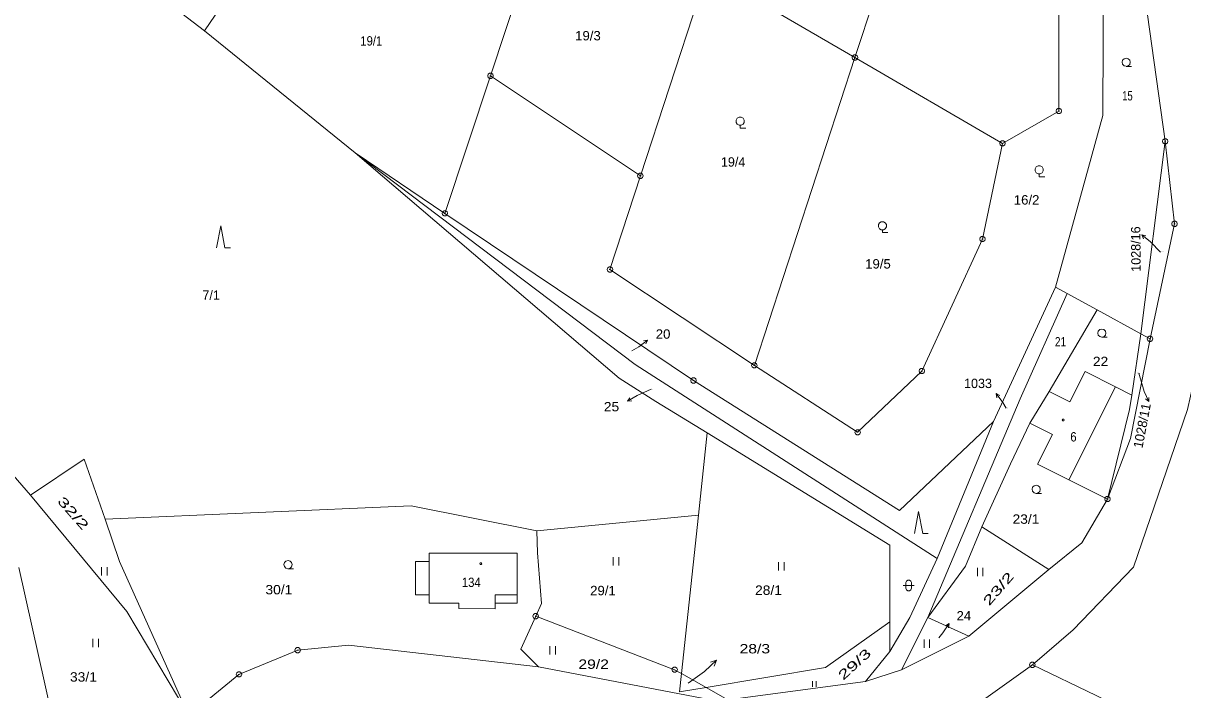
# Model space of a CAD drawing. Extents: x -687390 to -684106, y -954833 to -951648.
# Drawn here: x -686842.5 to -686632.4, y -952373.7 to -952252.9 of the extents above; entities that cross this region are included whole.
import ezdxf
from ezdxf.enums import TextEntityAlignment as Align

# ---------------------------------------------------------------- set-up
doc = ezdxf.new("R2010")
doc.units = 0
doc.header["$LTSCALE"] = 0.68
for name, color, linetype, lineweight in [('1', 7, 'Continuous', 13), ('3', 7, 'Continuous', 13), ('4', 7, 'Continuous', 13), ('5', 7, 'Continuous', 13), ('7', 7, 'Continuous', 13), ('8', 7, 'Continuous', 13)]:
    doc.layers.add(name, color=color, linetype=linetype, lineweight=lineweight)
doc.layers.add('2', color=7, linetype='Continuous')

msp = doc.modelspace()

# ---------------------------------------------------------------- linework, layer by layer
at = {"layer": '1'}
for p, q in [((-686675.65, -952209.59), (-686691.8, -952259.08)), ((-686635.56, -952274.27), (-686640.5, -952239.1)), ((-686718.58, -952243.49), (-686730.67, -952280.52)), ((-686809.68, -952254.23), (-686782.38, -952276.38)), ((-686691.8, -952259.08), (-686710.02, -952314.88)), ((-686757.85, -952262.42), (-686766.11, -952287.32)), ((-686782.38, -952276.38), (-686766.11, -952287.32)), ((-686766.11, -952287.32), (-686721.05, -952317.63)), ((-686653.31, -952301.85), (-686655.44, -952300.69)), ((-686653.31, -952301.85), (-686661.86, -952320.95)), ((-686647.9, -952304.83), (-686653.31, -952301.85)), ((-686647.9, -952304.83), (-686656.58, -952319.59)), ((-686641.62, -952320.24), (-686639.97, -952309.17)), ((-686650.06, -952315.96), (-686644.57, -952318.75)), ((-686683.73, -952341.14), (-686721.05, -952317.63)), ((-686644.57, -952318.75), (-686641.62, -952320.24)), ((-686678.57, -952360.57), (-686661.86, -952320.95)), ((-686660.07, -952325.36), (-686663.63, -952332.73)), ((-686656.02, -952327.37), (-686658.68, -952332.76)), ((-686668.79, -952344.1), (-686663.63, -952332.73)), ((-686658.68, -952332.76), (-686653.03, -952335.59)), ((-686653.03, -952335.59), (-686646.02, -952339.1)), ((-686827.68, -952342.74), (-686825.09, -952350.41)), ((-686685.45, -952347.42), (-686685.47, -952361.33)), ((-686768.96, -952348.91), (-686752.99, -952348.9)), ((-686752.99, -952348.9), (-686752.99, -952356.46)), ((-686676.91, -952349.84), (-686681.85, -952360.57)), ((-686843.35, -952351.48), (-686834.2, -952392.4)), ((-686812.53, -952378.29), (-686825.09, -952350.41)), ((-686756.99, -952358.96), (-686756.99, -952357.96)), ((-686685.48, -952366.74), (-686681.85, -952360.57)), ((-686671.14, -952363.91), (-686678.57, -952360.57)), ((-686671.14, -952363.91), (-686683.35, -952370.03)), ((-686723.22, -952370.73), (-686718.74, -952373.26)), ((-686714.84, -952375.47), (-686689.87, -952372.16))]:
    msp.add_line(p, q, dxfattribs=at)
for points in [[(-686731.65, -952183.41), (-686703.29, -952196.66), (-686675.65, -952209.59), (-686666.23, -952213.98), (-686660.17, -952222.54), (-686654.82, -952243.48), (-686654.84, -952268.78), (-686665.05, -952274.64), (-686691.8, -952259.08), (-686718.58, -952243.49), (-686746.23, -952227.39)], [(-686822.25, -952244.56), (-686809.68, -952254.23), (-686788.01, -952222.33)], [(-686757.85, -952262.42), (-686752.26, -952245.56), (-686788.01, -952222.33)], [(-686646.76, -952242.06), (-686646.86, -952269.57), (-686655.44, -952300.69)], [(-686665.05, -952274.64), (-686668.68, -952291.99), (-686679.67, -952315.89), (-686691.31, -952327), (-686710.02, -952314.88), (-686736.2, -952297.49), (-686730.67, -952280.52), (-686757.85, -952262.42)], [(-686635.56, -952274.27), (-686639.97, -952309.17), (-686647.9, -952304.83)], [(-686639.97, -952309.17), (-686638.31, -952310.06), (-686633.87, -952289.22), (-686635.56, -952274.27)], [(-686782.38, -952276.38), (-686731.61, -952314.68), (-686676.91, -952349.84), (-686666.7, -952325.03)], [(-686782.38, -952276.38), (-686734.55, -952317.16), (-686727.87, -952321.42), (-686718.58, -952327.11)], [(-686623.46, -952279.64), (-686624.96, -952282.62), (-686626.61, -952301.13), (-686631.53, -952322.87), (-686641.34, -952351.45), (-686652.22, -952362.81), (-686659.63, -952369.13), (-686648.08, -952374.71), (-686634.56, -952381.48), (-686619.46, -952386.48), (-686599.68, -952383.77), (-686603.98, -952392.18), (-686598.64, -952402.07), (-686585.34, -952406.85), (-686566.31, -952418.36), (-686550.51, -952430.86), (-686541.6, -952432.87), (-686525.56, -952458.37), (-686521.93, -952464.8)], [(-686866.54, -952281.02), (-686856.6, -952300.81), (-686857.44, -952303.87), (-686875.46, -952318.53), (-686854.46, -952336.7), (-686846.31, -952332.52), (-686841.22, -952338.37), (-686831.5, -952331.87), (-686827.68, -952342.74), (-686772.24, -952340.34), (-686749.44, -952344.82), (-686720.16, -952342.03), (-686723.22, -952370.73)], [(-686683.73, -952341.14), (-686666.7, -952325.03), (-686655.44, -952300.69)], [(-686638.31, -952310.06), (-686641.83, -952328.1), (-686646.02, -952339.1)], [(-686650.06, -952315.96), (-686652.82, -952321.45), (-686656.58, -952319.59), (-686660.07, -952325.36), (-686656.02, -952327.37)], [(-686646.02, -952339.1), (-686642.02, -952322.89), (-686641.62, -952320.24)], [(-686720.16, -952342.03), (-686718.58, -952327.11), (-686685.45, -952347.42)], [(-686812.53, -952378.29), (-686823.77, -952359.47), (-686841.22, -952338.37)], [(-686646.02, -952339.1), (-686650.68, -952347.05), (-686656.68, -952351.88)], [(-686749.44, -952344.82), (-686749.34, -952348.85), (-686748.59, -952357.99)], [(-686678.57, -952360.57), (-686671.73, -952351.28), (-686668.79, -952344.1)], [(-686668.79, -952344.1), (-686656.68, -952351.88), (-686671.14, -952363.91)], [(-686768.96, -952348.91), (-686768.97, -952350.4), (-686771.41, -952350.4), (-686771.41, -952356.42), (-686768.98, -952356.42), (-686768.98, -952357.93)], [(-686756.99, -952358.96), (-686763.56, -952358.93), (-686763.57, -952357.94), (-686768.98, -952357.93)], [(-686752.99, -952356.46), (-686752.99, -952357.97), (-686756.99, -952357.96)], [(-686748.59, -952357.99), (-686749.65, -952360.33), (-686752.37, -952366.32)], [(-686749.65, -952360.33), (-686724.47, -952370.01), (-686723.22, -952370.73), (-686723.57, -952374.05), (-686718.74, -952373.26)], [(-686685.48, -952366.74), (-686689.87, -952372.16), (-686683.35, -952370.03), (-686678.57, -952360.57)], [(-686718.74, -952373.26), (-686697.11, -952369.64), (-686685.47, -952361.33), (-686685.48, -952366.74)], [(-686749.13, -952369.49), (-686783.59, -952365.56), (-686792.79, -952366.48), (-686803.43, -952370.86), (-686812.53, -952378.29)], [(-686752.37, -952366.32), (-686749.13, -952369.49), (-686716.62, -952375.7)], [(-686701.59, -952385.52), (-686685.6, -952381.86), (-686670.21, -952376.71), (-686659.63, -952369.13)], [(-686716.62, -952375.7), (-686714.84, -952375.47), (-686718.74, -952373.26)]]:
    msp.add_lwpolyline(points, dxfattribs=at)
at = {"layer": '3'}
for p, q in [((-686735.6, -952349.62), (-686735.6, -952351.12)), ((-686734.6, -952351.12), (-686734.6, -952349.62)), ((-686828.34, -952351.43), (-686828.34, -952352.93)), ((-686827.34, -952352.93), (-686827.34, -952351.43)), ((-686705.65, -952350.55), (-686705.65, -952352.05)), ((-686704.65, -952352.05), (-686704.65, -952350.55)), ((-686669.6, -952351.57), (-686669.6, -952353.07)), ((-686668.6, -952353.07), (-686668.6, -952351.57)), ((-686829.91, -952364.42), (-686829.91, -952365.92)), ((-686828.91, -952365.92), (-686828.91, -952364.42)), ((-686679.28, -952364.53), (-686679.28, -952366.03)), ((-686678.28, -952366.03), (-686678.28, -952364.53)), ((-686747.08, -952365.77), (-686747.08, -952367.27)), ((-686746.08, -952367.27), (-686746.08, -952365.77)), ((-686699.495, -952372.085), (-686699.495, -952373.09)), ((-686698.825, -952373.09), (-686698.825, -952372.085))]:
    msp.add_line(p, q, dxfattribs=at)
for points in [[(-686642.63, -952260.68), (-686643.01, -952260.58), (-686643.28, -952260.31), (-686643.38, -952259.94), (-686643.28, -952259.57), (-686643.01, -952259.3), (-686642.64, -952259.2), (-686642.27, -952259.3), (-686642, -952259.57), (-686641.9, -952259.95), (-686642, -952260.33), (-686642.27, -952260.6), (-686642.65, -952260.7), (-686641.65, -952260.7)], [(-686712.61, -952271.36), (-686712.8, -952271.36), (-686713.14, -952271.17), (-686713.33, -952270.83), (-686713.33, -952270.44), (-686713.14, -952270.1), (-686712.8, -952269.91), (-686712.41, -952269.91), (-686712.07, -952270.1), (-686711.88, -952270.44), (-686711.88, -952270.83), (-686712.07, -952271.17), (-686712.41, -952271.36), (-686712.6, -952271.36), (-686712.6, -952271.89), (-686711.6, -952271.89)], [(-686658.41, -952280.17), (-686658.6, -952280.17), (-686658.94, -952279.98), (-686659.13, -952279.64), (-686659.13, -952279.25), (-686658.94, -952278.91), (-686658.6, -952278.72), (-686658.21, -952278.72), (-686657.87, -952278.91), (-686657.68, -952279.25), (-686657.68, -952279.64), (-686657.87, -952279.98), (-686658.21, -952280.17), (-686658.4, -952280.17), (-686658.4, -952280.7), (-686657.4, -952280.7)], [(-686686.83, -952290.29), (-686687.02, -952290.29), (-686687.36, -952290.1), (-686687.55, -952289.76), (-686687.55, -952289.37), (-686687.36, -952289.03), (-686687.02, -952288.84), (-686686.63, -952288.84), (-686686.29, -952289.03), (-686686.1, -952289.37), (-686686.1, -952289.76), (-686686.29, -952290.1), (-686686.63, -952290.29), (-686686.82, -952290.29), (-686686.82, -952290.82), (-686685.82, -952290.82)], [(-686807.49, -952293.58), (-686806.74, -952289.58), (-686805.99, -952293.58), (-686804.99, -952293.58)], [(-686647.04, -952309.76), (-686647.42, -952309.66), (-686647.69, -952309.39), (-686647.79, -952309.02), (-686647.69, -952308.65), (-686647.42, -952308.38), (-686647.05, -952308.28), (-686646.68, -952308.38), (-686646.41, -952308.65), (-686646.31, -952309.03), (-686646.41, -952309.41), (-686646.68, -952309.68), (-686647.06, -952309.78), (-686646.06, -952309.78)], [(-686658.94, -952338.06), (-686659.32, -952337.96), (-686659.59, -952337.69), (-686659.69, -952337.32), (-686659.59, -952336.95), (-686659.32, -952336.68), (-686658.95, -952336.58), (-686658.58, -952336.68), (-686658.31, -952336.95), (-686658.21, -952337.33), (-686658.31, -952337.71), (-686658.58, -952337.98), (-686658.96, -952338.08), (-686657.96, -952338.08)], [(-686681.02, -952345.34), (-686680.27, -952341.34), (-686679.52, -952345.34), (-686678.52, -952345.34)], [(-686794.53, -952351.71), (-686794.91, -952351.61), (-686795.18, -952351.34), (-686795.28, -952350.97), (-686795.18, -952350.6), (-686794.91, -952350.33), (-686794.54, -952350.23), (-686794.17, -952350.33), (-686793.9, -952350.6), (-686793.8, -952350.98), (-686793.9, -952351.36), (-686794.17, -952351.63), (-686794.55, -952351.73), (-686793.55, -952351.73)], [(-686683.08, -952354.74), (-686681.81, -952354.74), (-686681.08, -952354.74)]]:
    msp.add_lwpolyline(points, dxfattribs=at)
msp.add_lwpolyline([(-686682.58, -952354.24), (-686682.48, -952353.95), (-686682.23, -952353.77), (-686681.92, -952353.77), (-686681.67, -952353.95), (-686681.57, -952354.24), (-686681.57, -952355.24), (-686681.67, -952355.53), (-686681.92, -952355.71), (-686682.23, -952355.71), (-686682.48, -952355.53), (-686682.58, -952355.24)], close=True, dxfattribs=at)
at = {"layer": '4'}
for p, q in [((-686653.03, -952335.59), (-686644.57, -952318.75)), ((-686768.97, -952350.4), (-686768.98, -952356.42))]:
    msp.add_line(p, q, dxfattribs=at)
msp.add_lwpolyline([(-686756.99, -952357.96), (-686756.98, -952356.47), (-686752.99, -952356.46)], dxfattribs=at)
at = {"layer": '5'}
for points in [[(-686653.94, -952324.6), (-686653.85, -952324.75), (-686653.94, -952324.9), (-686654.12, -952324.9), (-686654.21, -952324.75), (-686654.12, -952324.6)], [(-686759.53, -952350.66), (-686759.44, -952350.81), (-686759.53, -952350.96), (-686759.71, -952350.96), (-686759.8, -952350.81), (-686759.71, -952350.66)]]:
    msp.add_lwpolyline(points, close=True, dxfattribs=at)
at = {"layer": '7'}
for p, q in [((-686639.788, -952291.235), (-686638.21, -952292.48)), ((-686636.42, -952294.35), (-686638.21, -952292.48)), ((-686732.24, -952312.23), (-686730.98, -952311.51)), ((-686729.389, -952310.281), (-686730.98, -952311.51)), ((-686640.37, -952316.28), (-686639.39, -952319.59)), ((-686733.003, -952321.361), (-686731.29, -952320.31)), ((-686728.71, -952319.19), (-686731.29, -952320.31)), ((-686666.227, -952319.986), (-686664.99, -952321.57)), ((-686638.553, -952321.418), (-686639.39, -952319.59)), ((-686664.38, -952322.64), (-686664.99, -952321.57)), ((-686674.738, -952361.659), (-686675.84, -952363.34)), ((-686676.61, -952364.21), (-686675.84, -952363.34)), ((-686716.9, -952368.309), (-686719.09, -952370.36)), ((-686722.04, -952372.43), (-686719.09, -952370.36))]:
    msp.add_line(p, q, dxfattribs=at)
for points in [[(-686639.47, -952291.913), (-686639.788, -952291.235), (-686639.055, -952291.387)], [(-686730.124, -952310.426), (-686729.389, -952310.281), (-686729.715, -952310.956)], [(-686666.079, -952320.72), (-686666.227, -952319.986), (-686665.551, -952320.308)], [(-686732.257, -952321.296), (-686733.003, -952321.361), (-686732.607, -952320.725)], [(-686638.528, -952320.669), (-686638.553, -952321.418), (-686639.137, -952320.948)], [(-686675.386, -952362.036), (-686674.738, -952361.659), (-686674.825, -952362.403)], [(-686717.972, -952368.628), (-686716.9, -952368.309), (-686717.288, -952369.358)]]:
    msp.add_lwpolyline(points, dxfattribs=at)
at = {"layer": '8'}
for p, q in [((-686691.92, -952259.08), (-686691.68, -952259.08)), ((-686757.97, -952262.42), (-686757.73, -952262.42)), ((-686654.96, -952268.78), (-686654.72, -952268.78)), ((-686635.68, -952274.27), (-686635.44, -952274.27)), ((-686665.17, -952274.64), (-686664.93, -952274.64)), ((-686730.79, -952280.52), (-686730.55, -952280.52)), ((-686766.23, -952287.32), (-686765.99, -952287.32)), ((-686633.99, -952289.22), (-686633.75, -952289.22)), ((-686668.8, -952291.99), (-686668.56, -952291.99)), ((-686736.32, -952297.49), (-686736.08, -952297.49)), ((-686638.43, -952310.06), (-686638.19, -952310.06)), ((-686710.14, -952314.88), (-686709.9, -952314.88)), ((-686679.79, -952315.89), (-686679.55, -952315.89)), ((-686721.17, -952317.63), (-686720.93, -952317.63)), ((-686691.43, -952327), (-686691.19, -952327)), ((-686646.14, -952339.1), (-686645.9, -952339.1)), ((-686749.77, -952360.33), (-686749.53, -952360.33)), ((-686792.91, -952366.48), (-686792.67, -952366.48)), ((-686803.55, -952370.86), (-686803.31, -952370.86)), ((-686724.59, -952370.01), (-686724.35, -952370.01)), ((-686659.75, -952369.13), (-686659.51, -952369.13))]:
    msp.add_line(p, q, dxfattribs=at)
for points in [[(-686691.65, -952258.6), (-686691.4, -952258.78), (-686691.3, -952259.07), (-686691.4, -952259.36), (-686691.65, -952259.54), (-686691.96, -952259.54), (-686692.21, -952259.36), (-686692.31, -952259.07), (-686692.21, -952258.78), (-686691.96, -952258.6)], [(-686757.7, -952261.94), (-686757.45, -952262.12), (-686757.35, -952262.41), (-686757.45, -952262.7), (-686757.7, -952262.88), (-686758.01, -952262.88), (-686758.26, -952262.7), (-686758.36, -952262.41), (-686758.26, -952262.12), (-686758.01, -952261.94)], [(-686654.69, -952268.3), (-686654.44, -952268.48), (-686654.34, -952268.77), (-686654.44, -952269.06), (-686654.69, -952269.24), (-686655, -952269.24), (-686655.25, -952269.06), (-686655.35, -952268.77), (-686655.25, -952268.48), (-686655, -952268.3)], [(-686664.9, -952274.16), (-686664.65, -952274.34), (-686664.55, -952274.63), (-686664.65, -952274.92), (-686664.9, -952275.1), (-686665.21, -952275.1), (-686665.46, -952274.92), (-686665.56, -952274.63), (-686665.46, -952274.34), (-686665.21, -952274.16)], [(-686635.41, -952273.79), (-686635.16, -952273.97), (-686635.06, -952274.26), (-686635.16, -952274.55), (-686635.41, -952274.73), (-686635.72, -952274.73), (-686635.97, -952274.55), (-686636.07, -952274.26), (-686635.97, -952273.97), (-686635.72, -952273.79)], [(-686730.52, -952280.04), (-686730.27, -952280.22), (-686730.17, -952280.51), (-686730.27, -952280.8), (-686730.52, -952280.98), (-686730.83, -952280.98), (-686731.08, -952280.8), (-686731.18, -952280.51), (-686731.08, -952280.22), (-686730.83, -952280.04)], [(-686765.96, -952286.84), (-686765.71, -952287.02), (-686765.61, -952287.31), (-686765.71, -952287.6), (-686765.96, -952287.78), (-686766.27, -952287.78), (-686766.52, -952287.6), (-686766.62, -952287.31), (-686766.52, -952287.02), (-686766.27, -952286.84)], [(-686633.72, -952288.74), (-686633.47, -952288.92), (-686633.37, -952289.21), (-686633.47, -952289.5), (-686633.72, -952289.68), (-686634.03, -952289.68), (-686634.28, -952289.5), (-686634.38, -952289.21), (-686634.28, -952288.92), (-686634.03, -952288.74)], [(-686668.53, -952291.51), (-686668.28, -952291.69), (-686668.18, -952291.98), (-686668.28, -952292.27), (-686668.53, -952292.45), (-686668.84, -952292.45), (-686669.09, -952292.27), (-686669.19, -952291.98), (-686669.09, -952291.69), (-686668.84, -952291.51)], [(-686736.05, -952297.01), (-686735.8, -952297.19), (-686735.7, -952297.48), (-686735.8, -952297.77), (-686736.05, -952297.95), (-686736.36, -952297.95), (-686736.61, -952297.77), (-686736.71, -952297.48), (-686736.61, -952297.19), (-686736.36, -952297.01)], [(-686638.16, -952309.58), (-686637.91, -952309.76), (-686637.81, -952310.05), (-686637.91, -952310.34), (-686638.16, -952310.52), (-686638.47, -952310.52), (-686638.72, -952310.34), (-686638.82, -952310.05), (-686638.72, -952309.76), (-686638.47, -952309.58)], [(-686709.87, -952314.4), (-686709.62, -952314.58), (-686709.52, -952314.87), (-686709.62, -952315.16), (-686709.87, -952315.34), (-686710.18, -952315.34), (-686710.43, -952315.16), (-686710.53, -952314.87), (-686710.43, -952314.58), (-686710.18, -952314.4)], [(-686679.52, -952315.41), (-686679.27, -952315.59), (-686679.17, -952315.88), (-686679.27, -952316.17), (-686679.52, -952316.35), (-686679.83, -952316.35), (-686680.08, -952316.17), (-686680.18, -952315.88), (-686680.08, -952315.59), (-686679.83, -952315.41)], [(-686720.9, -952317.15), (-686720.65, -952317.33), (-686720.55, -952317.62), (-686720.65, -952317.91), (-686720.9, -952318.09), (-686721.21, -952318.09), (-686721.46, -952317.91), (-686721.56, -952317.62), (-686721.46, -952317.33), (-686721.21, -952317.15)], [(-686691.16, -952326.52), (-686690.91, -952326.7), (-686690.81, -952326.99), (-686690.91, -952327.28), (-686691.16, -952327.46), (-686691.47, -952327.46), (-686691.72, -952327.28), (-686691.82, -952326.99), (-686691.72, -952326.7), (-686691.47, -952326.52)], [(-686645.87, -952338.62), (-686645.62, -952338.8), (-686645.52, -952339.09), (-686645.62, -952339.38), (-686645.87, -952339.56), (-686646.18, -952339.56), (-686646.43, -952339.38), (-686646.53, -952339.09), (-686646.43, -952338.8), (-686646.18, -952338.62)], [(-686749.5, -952359.85), (-686749.25, -952360.03), (-686749.15, -952360.32), (-686749.25, -952360.61), (-686749.5, -952360.79), (-686749.81, -952360.79), (-686750.06, -952360.61), (-686750.16, -952360.32), (-686750.06, -952360.03), (-686749.81, -952359.85)], [(-686792.64, -952366), (-686792.39, -952366.18), (-686792.29, -952366.47), (-686792.39, -952366.76), (-686792.64, -952366.94), (-686792.95, -952366.94), (-686793.2, -952366.76), (-686793.3, -952366.47), (-686793.2, -952366.18), (-686792.95, -952366)], [(-686659.48, -952368.65), (-686659.23, -952368.83), (-686659.13, -952369.12), (-686659.23, -952369.41), (-686659.48, -952369.59), (-686659.79, -952369.59), (-686660.04, -952369.41), (-686660.14, -952369.12), (-686660.04, -952368.83), (-686659.79, -952368.65)], [(-686803.28, -952370.38), (-686803.03, -952370.56), (-686802.93, -952370.85), (-686803.03, -952371.14), (-686803.28, -952371.32), (-686803.59, -952371.32), (-686803.84, -952371.14), (-686803.94, -952370.85), (-686803.84, -952370.56), (-686803.59, -952370.38)], [(-686724.32, -952369.53), (-686724.07, -952369.71), (-686723.97, -952370), (-686724.07, -952370.29), (-686724.32, -952370.47), (-686724.63, -952370.47), (-686724.88, -952370.29), (-686724.98, -952370), (-686724.88, -952369.71), (-686724.63, -952369.53)]]:
    msp.add_lwpolyline(points, close=True, dxfattribs=at)

# ---------------------------------------------------------------- texts
at = {"layer": '2'}
for s, height, width, p in [('19/1', 1.7, 0.9, (-686781.445, -952256.92)), ('19/3', 1.7, 1.05, (-686742.505, -952255.98)), ('15', 1.7, 0.75, (-686643.355, -952266.86)), ('16/2', 1.7, 1.05, (-686663.005, -952285.73)), ('21', 1.7, 0.8, (-686655.555, -952311.44)), ('20', 0.1, 1.05, (-686732.212, -952312.23)), ('22', 1.7, 1.1, (-686648.675, -952315.01)), ('25', 0.1, 1.1, (-686728.682, -952319.19)), ('6', 1.7, 0.9, (-686652.766, -952328.66)), ('23/1', 1.7, 1.1, (-686663.235, -952343.57)), ('134', 1.7, 0.9, (-686763.035, -952355.03)), ('30/1', 1.7, 1.1, (-686798.635, -952356.36)), ('29/1', 1.7, 1.05, (-686739.785, -952356.52)), ('28/1', 1.7, 1.1, (-686709.895, -952356.45)), ('24', 0.1, 1.05, (-686676.582, -952364.21)), ('29/2', 1.7, 1.25, (-686741.915, -952369.86)), ('33/1', 1.7, 1.1, (-686834.055, -952372.17)), ('28/3', 0.1, 1.25, (-686722.012, -952372.43))]:
    msp.add_text(s, height=height, dxfattribs=dict(at, width=width)).set_placement(p)
msp.add_text('19/4', height=1.7, dxfattribs=at).set_placement((-686713.87, -952278.86), align=Align.CENTER)
for s, height, p in [('1028/16', 0.1, (-686636.374, -952294.35)), ('7/1', 1.7, (-686810.055, -952302.98)), ('1033', 0.1, (-686664.334, -952322.64))]:
    msp.add_text(s, height=height, dxfattribs=at).set_placement(p)
for s, height, width, p in [('19/5', 1.7, 1.05, (-686687.62, -952297.32)), ('1028/11', 0.1, 0.95, (-686640.37, -952316.28))]:
    msp.add_text(s, height=height, dxfattribs=dict(at, width=width)).set_placement(p, align=Align.CENTER)
at = {"layer": '2', "width": 1.6}
for s, rotation, p in [('32/2', 311.517, (-686836.465, -952339.566)), ('23/2', 49.16, (-686667.469, -952358.561)), ('29/3', 42.399, (-686693.919, -952372.02))]:
    msp.add_text(s, height=1.7, rotation=rotation, dxfattribs=at).set_placement(p)
at = {"layer": '7'}
msp.add_text('1028/16', height=1.7, rotation=90.355, dxfattribs=at).set_placement((-686640.067, -952289.686), align=Align.RIGHT)
for s, width, p in [('20', 1.05, (-686727.895, -952310.04)), ('24', 1.05, (-686673.385, -952361.09)), ('28/3', 1.25, (-686712.705, -952367.06))]:
    msp.add_text(s, height=1.7, dxfattribs=dict(at, width=width)).set_placement(p)
msp.add_text('1033', height=1.7, dxfattribs=at).set_placement((-686666.966, -952318.98), align=Align.RIGHT)
at = {"layer": '7', "width": 1.1}
msp.add_text('25', height=1.7, dxfattribs=at).set_placement((-686734.526, -952323.2), align=Align.RIGHT)
at = {"layer": '7'}
msp.add_text('1028/11', height=1.7, rotation=79.183, dxfattribs=at).set_placement((-686639.693, -952329.978))

doc.saveas('drawing.dxf')
